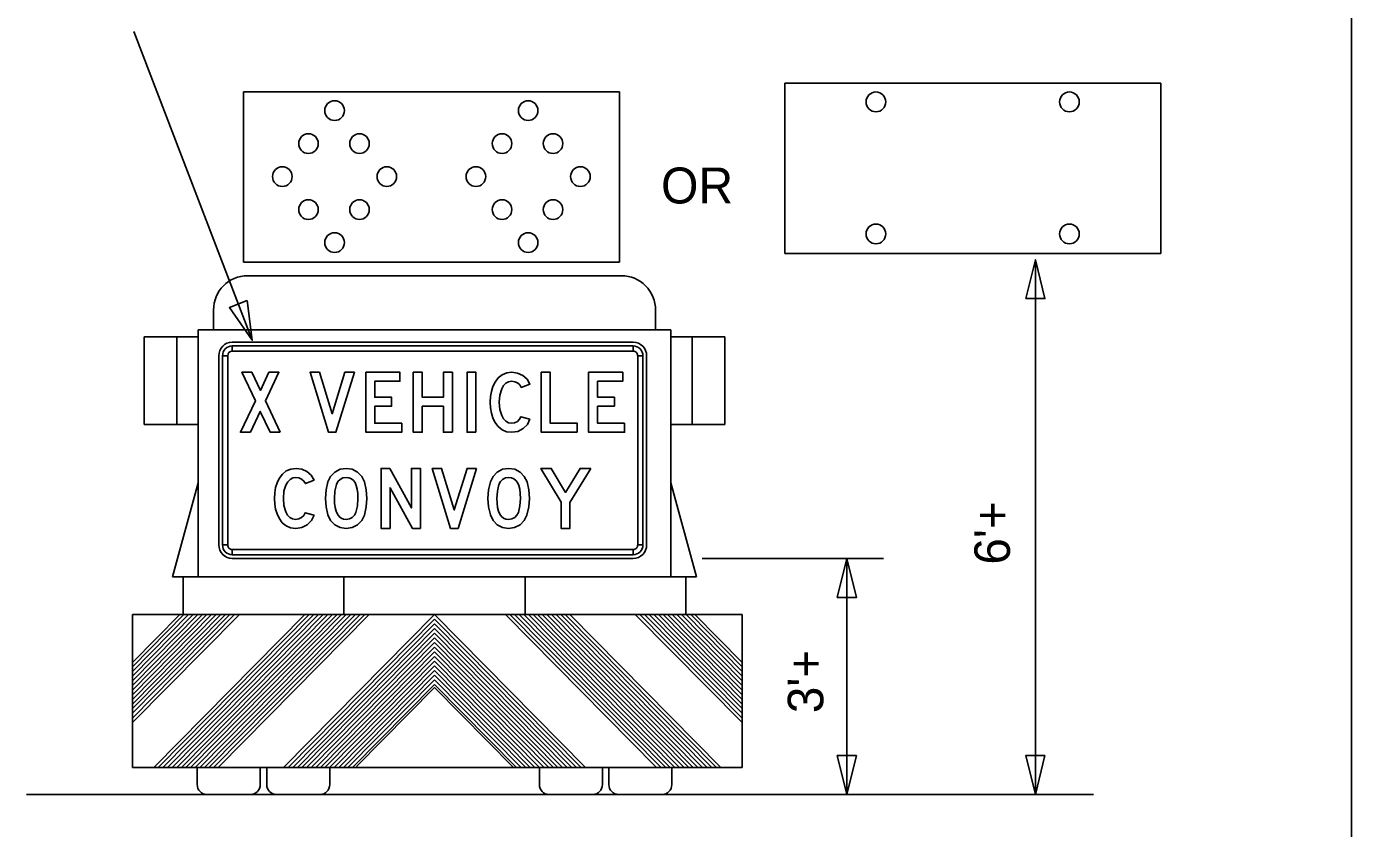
# Model space of a CAD drawing. Extents: x 1416408 to 1429341, y 372694 to 383211.
# Drawn here: x 1427728.6 to 1428099.1, y 373595.9 to 373820.1 of the extents above; entities that cross this region are included whole.
import ezdxf

# ---------------------------------------------------------------- set-up
doc = ezdxf.new("R2010")
doc.units = 0
doc.layers.add('Working Level 1', color=7, linetype='Continuous')

msp = doc.modelspace()

# ---------------------------------------------------------------- linework, layer by layer
at = {"layer": 'Working Level 1'}
for p, q in [((1428099.08, 374447.3), (1428099.08, 372727.17)), ((1427791.75, 373732.38), (1427758.6, 373818.69)), ((1427940.68, 373756.63), (1427940.68, 373804.25)), ((1427940.68, 373804.25), (1428045.73, 373804.25)), ((1428045.73, 373756.63), (1428045.73, 373804.25)), ((1427789.34, 373801.82), (1427894.39, 373801.82)), ((1427789.34, 373754.2), (1427789.34, 373801.82)), ((1427894.39, 373754.2), (1427894.39, 373801.82)), ((1427940.68, 373756.63), (1428045.73, 373756.63)), ((1427789.34, 373754.2), (1427894.39, 373754.2)), ((1428010.69, 373605.38), (1428010.69, 373754.93)), ((1428010.69, 373754.93), (1428010.69, 373746.16)), ((1427790.42, 373750.44), (1427894.99, 373750.44)), ((1427780.92, 373735.32), (1427780.92, 373740.84)), ((1427904.5, 373735.32), (1427904.5, 373740.84)), ((1427776.61, 373666.22), (1427776.61, 373735.32)), ((1427776.61, 373735.32), (1427908.81, 373735.32)), ((1427908.81, 373666.22), (1427908.81, 373735.32)), ((1427761.52, 373708.81), (1427761.52, 373733.37)), ((1427761.52, 373733.37), (1427776.61, 373733.37)), ((1427770.66, 373708.81), (1427770.66, 373733.37)), ((1427898.26, 373731.85), (1427786.12, 373731.85)), ((1427786.12, 373729.33), (1427786.12, 373730.8)), ((1427898.26, 373730.8), (1427898.26, 373729.33)), ((1427923.9, 373733.37), (1427908.81, 373733.37)), ((1427914.76, 373708.81), (1427914.76, 373733.37)), ((1427923.9, 373708.81), (1427923.9, 373733.37)), ((1427782.38, 373728.07), (1427782.38, 373675.16)), ((1427783.42, 373728.07), (1427784.87, 373728.07)), ((1427899.51, 373728.07), (1427900.96, 373728.07)), ((1427902, 373675.16), (1427902, 373728.07)), ((1427761.52, 373708.81), (1427776.61, 373708.81)), ((1427923.9, 373708.81), (1427908.81, 373708.81)), ((1427776.61, 373692.54), (1427769.46, 373666.22)), ((1427908.81, 373692.54), (1427915.96, 373666.22)), ((1427784.87, 373675.16), (1427783.42, 373675.16)), ((1427900.96, 373675.16), (1427899.51, 373675.16)), ((1427786.12, 373672.43), (1427786.12, 373673.9)), ((1427786.12, 373671.38), (1427898.26, 373671.38)), ((1427898.26, 373673.9), (1427898.26, 373672.43)), ((1427917.53, 373671.38), (1427968.23, 373671.38)), ((1427958.01, 373605.38), (1427958.01, 373671.38)), ((1427958.01, 373671.38), (1427958.01, 373662.47)), ((1427769.46, 373666.22), (1427915.96, 373666.22)), ((1427772.43, 373655.67), (1427772.43, 373666.22)), ((1427817.34, 373655.67), (1427817.34, 373666.03)), ((1427868.08, 373655.67), (1427868.08, 373666.03)), ((1427912.99, 373655.67), (1427912.99, 373666.22)), ((1427758.23, 373655.67), (1427928.73, 373655.67)), ((1427758.23, 373655.67), (1427928.73, 373655.67)), ((1427758.23, 373655.67), (1427928.73, 373655.67)), ((1427758.23, 373655.67), (1427928.73, 373655.67)), ((1427758.23, 373612.98), (1427758.23, 373655.67)), ((1427758.23, 373642.31), (1427771.45, 373655.67)), ((1427758.23, 373626.77), (1427786.82, 373655.67)), ((1427758.23, 373628.08), (1427785.52, 373655.67)), ((1427758.23, 373629.39), (1427784.23, 373655.67)), ((1427758.23, 373630.68), (1427782.96, 373655.67)), ((1427758.23, 373631.98), (1427781.66, 373655.67)), ((1427758.23, 373633.29), (1427780.37, 373655.67)), ((1427758.23, 373634.58), (1427779.09, 373655.67)), ((1427758.23, 373635.89), (1427777.8, 373655.67)), ((1427758.23, 373637.2), (1427776.51, 373655.67)), ((1427758.23, 373638.5), (1427775.21, 373655.67)), ((1427758.23, 373639.79), (1427773.94, 373655.67)), ((1427758.23, 373641.1), (1427772.64, 373655.67)), ((1427758.23, 373625.47), (1427788.07, 373655.63)), ((1427764.18, 373612.98), (1427806.41, 373655.67)), ((1427765.47, 373612.98), (1427807.7, 373655.67)), ((1427766.76, 373612.98), (1427808.99, 373655.67)), ((1427768.05, 373612.98), (1427810.28, 373655.67)), ((1427769.33, 373612.98), (1427811.56, 373655.67)), ((1427770.62, 373612.98), (1427812.85, 373655.67)), ((1427771.92, 373612.98), (1427814.14, 373655.67)), ((1427773.21, 373612.98), (1427815.44, 373655.67)), ((1427774.48, 373612.98), (1427816.71, 373655.67)), ((1427775.78, 373612.98), (1427818.01, 373655.67)), ((1427777.07, 373612.98), (1427819.3, 373655.67)), ((1427778.35, 373612.98), (1427820.57, 373655.67)), ((1427779.64, 373612.98), (1427821.87, 373655.67)), ((1427780.93, 373612.98), (1427823.14, 373655.65)), ((1427782.22, 373612.98), (1427824.45, 373655.67)), ((1427800.48, 373612.98), (1427842.71, 373655.67)), ((1427801.77, 373612.98), (1427842.71, 373654.37)), ((1427803.06, 373612.98), (1427842.71, 373653.06)), ((1427884.94, 373612.98), (1427842.71, 373655.67)), ((1427883.59, 373613.05), (1427842.71, 373654.37)), ((1427882.37, 373612.98), (1427842.71, 373653.06)), ((1427904.75, 373612.98), (1427862.52, 373655.67)), ((1427906.03, 373612.98), (1427863.82, 373655.65)), ((1427907.33, 373612.98), (1427865.1, 373655.67)), ((1427908.62, 373612.98), (1427866.39, 373655.67)), ((1427909.9, 373612.98), (1427867.67, 373655.67)), ((1427911.19, 373612.98), (1427868.96, 373655.67)), ((1427912.48, 373612.98), (1427870.25, 373655.67)), ((1427913.76, 373612.98), (1427871.53, 373655.67)), ((1427915.05, 373612.98), (1427872.82, 373655.67)), ((1427916.34, 373612.98), (1427874.12, 373655.67)), ((1427917.64, 373612.98), (1427875.41, 373655.67)), ((1427918.91, 373612.98), (1427876.69, 373655.67)), ((1427920.21, 373612.98), (1427877.98, 373655.67)), ((1427921.5, 373612.98), (1427879.27, 373655.67)), ((1427922.78, 373612.98), (1427880.56, 373655.67)), ((1427928.73, 373625.47), (1427898.9, 373655.63)), ((1427928.73, 373626.77), (1427900.15, 373655.67)), ((1427928.73, 373628.08), (1427901.44, 373655.67)), ((1427928.73, 373629.39), (1427902.74, 373655.67)), ((1427928.73, 373630.68), (1427904.01, 373655.67)), ((1427928.73, 373631.98), (1427905.3, 373655.67)), ((1427928.73, 373633.29), (1427906.6, 373655.67)), ((1427928.73, 373634.58), (1427907.87, 373655.67)), ((1427928.73, 373635.89), (1427909.17, 373655.67)), ((1427928.73, 373637.2), (1427910.46, 373655.67)), ((1427928.73, 373638.5), (1427911.75, 373655.67)), ((1427928.73, 373639.79), (1427913.03, 373655.67)), ((1427928.73, 373641.1), (1427914.32, 373655.67)), ((1427928.73, 373642.31), (1427915.52, 373655.67)), ((1427928.73, 373612.98), (1427928.73, 373655.67)), ((1427804.35, 373612.98), (1427842.71, 373651.76)), ((1427805.63, 373612.98), (1427842.71, 373650.47)), ((1427806.92, 373612.98), (1427842.71, 373649.16)), ((1427881.08, 373612.98), (1427842.71, 373651.76)), ((1427879.8, 373612.98), (1427842.71, 373650.47)), ((1427878.51, 373612.98), (1427842.71, 373649.16)), ((1427808.21, 373612.98), (1427842.71, 373647.85)), ((1427809.49, 373612.98), (1427842.71, 373646.56)), ((1427810.78, 373612.98), (1427842.71, 373645.26)), ((1427877.21, 373612.98), (1427842.71, 373647.85)), ((1427875.94, 373612.98), (1427842.71, 373646.56)), ((1427874.64, 373612.98), (1427842.71, 373645.26)), ((1427812.08, 373612.98), (1427842.71, 373643.95)), ((1427813.37, 373612.98), (1427842.71, 373642.64)), ((1427814.65, 373612.98), (1427842.71, 373641.35)), ((1427873.35, 373612.98), (1427842.71, 373643.95)), ((1427872.06, 373612.98), (1427842.71, 373642.64)), ((1427870.78, 373612.98), (1427842.71, 373641.35)), ((1427815.94, 373612.98), (1427842.71, 373640.04)), ((1427817.23, 373612.98), (1427842.71, 373638.73)), ((1427818.51, 373612.98), (1427842.71, 373637.45)), ((1427869.49, 373612.98), (1427842.71, 373640.04)), ((1427868.2, 373612.98), (1427842.71, 373638.73)), ((1427866.92, 373612.98), (1427842.71, 373637.45)), ((1427819.79, 373612.98), (1427842.71, 373636.15)), ((1427820.88, 373613.23), (1427842.71, 373635.3)), ((1427865.63, 373612.98), (1427842.71, 373636.15)), ((1427864.79, 373612.98), (1427842.71, 373635.3)), ((1427758.23, 373612.98), (1427928.73, 373612.98)), ((1427758.23, 373612.98), (1427928.73, 373612.98)), ((1427758.23, 373612.98), (1427928.73, 373612.98)), ((1427758.23, 373612.98), (1427928.73, 373612.98)), ((1427776.35, 373608.14), (1427776.35, 373612.98)), ((1427793.97, 373608.14), (1427793.97, 373612.98)), ((1427795.79, 373608.14), (1427795.79, 373612.98)), ((1427813.41, 373608.14), (1427813.41, 373612.98)), ((1427872.01, 373608.14), (1427872.01, 373612.98)), ((1427889.63, 373608.14), (1427889.63, 373612.98)), ((1427891.45, 373608.14), (1427891.45, 373612.98)), ((1427909.07, 373608.14), (1427909.07, 373612.98)), ((1427728.62, 373605.38), (1428026.92, 373605.38)), ((1427776.35, 373605.38), (1427793.97, 373605.38)), ((1427776.35, 373605.38), (1427793.97, 373605.38)), ((1427776.35, 373605.38), (1427793.97, 373605.38)), ((1427776.35, 373605.38), (1427793.97, 373605.38)), ((1427795.79, 373605.38), (1427813.41, 373605.38)), ((1427795.79, 373605.38), (1427813.41, 373605.38)), ((1427795.79, 373605.38), (1427813.41, 373605.38)), ((1427795.79, 373605.38), (1427813.41, 373605.38)), ((1427889.63, 373605.38), (1427872.01, 373605.38)), ((1427889.63, 373605.38), (1427872.01, 373605.38)), ((1427889.63, 373605.38), (1427872.01, 373605.38)), ((1427889.63, 373605.38), (1427872.01, 373605.38)), ((1427909.07, 373605.38), (1427891.45, 373605.38)), ((1427909.07, 373605.38), (1427891.45, 373605.38)), ((1427909.07, 373605.38), (1427891.45, 373605.38)), ((1427909.07, 373605.38), (1427891.45, 373605.38))]:
    msp.add_line(p, q, dxfattribs=at)
for points in [[(1428008, 373744.04), (1428010.69, 373754.93), (1428013.38, 373744.04)], [(1427790.36, 373743.51), (1427791.75, 373732.38), (1427785.34, 373741.54)], [(1427898.26, 373730.8), (1427786.12, 373730.8), (1427786.12, 373729.33), (1427898.26, 373729.33), (1427898.26, 373730.8)], [(1427783.42, 373728.07), (1427783.42, 373675.16), (1427784.87, 373675.16), (1427784.87, 373728.07), (1427783.42, 373728.07)], [(1427900.96, 373675.16), (1427900.96, 373728.07), (1427899.51, 373728.07), (1427899.51, 373675.16), (1427900.96, 373675.16)], [(1427799.54, 373706.66), (1427795.41, 373715.45), (1427799.2, 373723.45), (1427796.42, 373723.45), (1427794.01, 373718.38), (1427791.62, 373723.45), (1427788.84, 373723.45), (1427792.62, 373715.43), (1427788.45, 373706.66), (1427791.23, 373706.66), (1427794, 373712.49), (1427796.77, 373706.66)], [(1427820.3, 373723.45), (1427817.67, 373723.45), (1427814.1, 373711.85), (1427810.54, 373723.45), (1427807.92, 373723.45), (1427813.07, 373706.66), (1427815.13, 373706.66)], [(1427833.54, 373709.19), (1427826.01, 373709.19), (1427826.01, 373713.95), (1427830.71, 373713.95), (1427830.71, 373716.48), (1427826.01, 373716.48), (1427826.01, 373720.92), (1427833.04, 373720.92), (1427833.04, 373723.45), (1427823.5, 373723.45), (1427823.5, 373706.66), (1427833.54, 373706.66)], [(1427847.71, 373706.66), (1427847.71, 373723.45), (1427845.2, 373723.45), (1427845.2, 373716.48), (1427839.25, 373716.48), (1427839.25, 373723.45), (1427836.74, 373723.45), (1427836.74, 373706.66), (1427839.25, 373706.66), (1427839.25, 373713.95), (1427845.2, 373713.95), (1427845.2, 373706.66)], [(1427854.3, 373706.66), (1427854.3, 373723.45), (1427851.8, 373723.45), (1427851.8, 373706.66)], [(1427869.37, 373710.38), (1427866.86, 373711.03), (1427866.49, 373710.29), (1427865.88, 373709.71), (1427865.1, 373709.32), (1427864.24, 373709.19), (1427863.37, 373709.32), (1427862.62, 373709.73), (1427861.98, 373710.4), (1427861.48, 373711.33), (1427860.96, 373713.05), (1427860.79, 373715.05), (1427860.97, 373717.07), (1427861.49, 373718.79), (1427862.02, 373719.72), (1427862.67, 373720.38), (1427863.43, 373720.78), (1427864.32, 373720.92), (1427865.15, 373720.8), (1427865.91, 373720.45), (1427866.54, 373719.9), (1427866.97, 373719.2), (1427869.37, 373720.16), (1427868.56, 373721.5), (1427867.38, 373722.55), (1427865.94, 373723.22), (1427864.36, 373723.45), (1427862.9, 373723.28), (1427861.62, 373722.75), (1427860.53, 373721.87), (1427859.62, 373720.65), (1427859.04, 373719.44), (1427858.62, 373718.1), (1427858.37, 373716.64), (1427858.29, 373715.06), (1427858.36, 373713.49), (1427858.61, 373712.03), (1427859.03, 373710.7), (1427859.61, 373709.49), (1427860.5, 373708.25), (1427861.57, 373707.36), (1427862.83, 373706.83), (1427864.28, 373706.66), (1427865.97, 373706.91), (1427867.48, 373707.69), (1427868.67, 373708.88)], [(1427882.61, 373706.66), (1427882.61, 373709.19), (1427875.07, 373709.19), (1427875.07, 373723.45), (1427872.56, 373723.45), (1427872.56, 373706.66)], [(1427895.85, 373709.19), (1427888.31, 373709.19), (1427888.31, 373713.95), (1427893.01, 373713.95), (1427893.01, 373716.48), (1427888.31, 373716.48), (1427888.31, 373720.92), (1427895.34, 373720.92), (1427895.34, 373723.45), (1427885.8, 373723.45), (1427885.8, 373706.66), (1427895.85, 373706.66)], [(1427809.02, 373683.51), (1427806.51, 373684.15), (1427806.13, 373683.41), (1427805.53, 373682.83), (1427804.75, 373682.45), (1427803.88, 373682.32), (1427803.01, 373682.45), (1427802.26, 373682.85), (1427801.63, 373683.52), (1427801.12, 373684.45), (1427800.6, 373686.18), (1427800.44, 373688.18), (1427800.61, 373690.19), (1427801.14, 373691.92), (1427801.66, 373692.84), (1427802.31, 373693.51), (1427803.07, 373693.91), (1427803.96, 373694.04), (1427804.79, 373693.92), (1427805.55, 373693.58), (1427806.18, 373693.03), (1427806.61, 373692.32), (1427809.02, 373693.28), (1427808.2, 373694.63), (1427807.02, 373695.68), (1427805.58, 373696.35), (1427804, 373696.58), (1427802.54, 373696.4), (1427801.26, 373695.88), (1427800.17, 373695), (1427799.27, 373693.78), (1427798.68, 373692.56), (1427798.26, 373691.23), (1427798.01, 373689.77), (1427797.93, 373688.19), (1427798.01, 373686.61), (1427798.26, 373685.15), (1427798.67, 373683.82), (1427799.25, 373682.61), (1427800.14, 373681.37), (1427801.22, 373680.49), (1427802.48, 373679.95), (1427803.92, 373679.78), (1427805.61, 373680.04), (1427807.13, 373680.81), (1427808.31, 373682.01)], [(1427823.8, 373688.19), (1427823.63, 373690.59), (1427823.13, 373692.83), (1427822.38, 373694.34), (1427821.19, 373695.54), (1427819.69, 373696.31), (1427818, 373696.58), (1427816.31, 373696.31), (1427814.81, 373695.54), (1427813.63, 373694.34), (1427812.88, 373692.81), (1427812.37, 373690.57), (1427812.21, 373688.19), (1427812.37, 373685.81), (1427812.88, 373683.56), (1427813.63, 373682.03), (1427814.81, 373680.83), (1427816.31, 373680.04), (1427818, 373679.78), (1427819.68, 373680.04), (1427821.18, 373680.81), (1427822.36, 373682.01), (1427823.12, 373683.53), (1427823.63, 373685.78)], [(1427821.3, 373688.18), (1427821.15, 373686.14), (1427820.71, 373684.24), (1427820.31, 373683.45), (1427819.69, 373682.84), (1427818.9, 373682.45), (1427818.02, 373682.32), (1427817.24, 373682.4), (1427816.57, 373682.68), (1427816, 373683.14), (1427815.54, 373683.78), (1427815.18, 373684.6), (1427814.92, 373685.61), (1427814.76, 373686.8), (1427814.71, 373688.18), (1427814.86, 373690.21), (1427815.3, 373692.1), (1427815.7, 373692.89), (1427816.32, 373693.51), (1427817.11, 373693.91), (1427818.02, 373694.04), (1427818.78, 373693.95), (1427819.45, 373693.68), (1427820.01, 373693.22), (1427820.47, 373692.58), (1427820.83, 373691.75), (1427821.09, 373690.75), (1427821.24, 373689.55)], [(1427838.75, 373679.78), (1427838.75, 373696.58), (1427836.25, 373696.58), (1427836.25, 373685.54), (1427830.19, 373696.58), (1427827.78, 373696.58), (1427827.78, 373679.78), (1427830.29, 373679.78), (1427830.29, 373691.18), (1427836.54, 373679.78)], [(1427854.43, 373696.58), (1427851.81, 373696.58), (1427848.24, 373684.97), (1427844.68, 373696.58), (1427842.06, 373696.58), (1427847.21, 373679.78), (1427849.27, 373679.78)], [(1427869.23, 373688.19), (1427869.06, 373690.59), (1427868.56, 373692.83), (1427867.81, 373694.34), (1427866.62, 373695.54), (1427865.12, 373696.31), (1427863.43, 373696.58), (1427861.74, 373696.31), (1427860.24, 373695.54), (1427859.06, 373694.34), (1427858.31, 373692.81), (1427857.8, 373690.57), (1427857.64, 373688.19), (1427857.8, 373685.81), (1427858.31, 373683.56), (1427859.06, 373682.03), (1427860.24, 373680.83), (1427861.74, 373680.04), (1427863.43, 373679.78), (1427865.11, 373680.04), (1427866.61, 373680.81), (1427867.79, 373682.01), (1427868.54, 373683.53), (1427869.06, 373685.78)], [(1427866.73, 373688.18), (1427866.58, 373686.14), (1427866.14, 373684.24), (1427865.74, 373683.45), (1427865.12, 373682.84), (1427864.33, 373682.45), (1427863.45, 373682.32), (1427862.67, 373682.4), (1427862, 373682.68), (1427861.43, 373683.14), (1427860.97, 373683.78), (1427860.6, 373684.6), (1427860.35, 373685.61), (1427860.19, 373686.8), (1427860.14, 373688.18), (1427860.29, 373690.21), (1427860.73, 373692.1), (1427861.13, 373692.89), (1427861.75, 373693.51), (1427862.54, 373693.91), (1427863.45, 373694.04), (1427864.21, 373693.95), (1427864.88, 373693.68), (1427865.44, 373693.22), (1427865.9, 373692.58), (1427866.26, 373691.75), (1427866.52, 373690.75), (1427866.67, 373689.55)], [(1427886.36, 373696.58), (1427883.41, 373696.58), (1427879.34, 373689.87), (1427875.35, 373696.58), (1427872.43, 373696.58), (1427878.08, 373687.14), (1427878.08, 373679.78), (1427880.58, 373679.78), (1427880.58, 373687.07)], [(1427786.12, 373672.43), (1427898.26, 373672.43), (1427898.26, 373673.9), (1427786.12, 373673.9), (1427786.12, 373672.43)], [(1427955.32, 373660.5), (1427958.01, 373671.38), (1427960.7, 373660.5)], [(1427960.7, 373616.26), (1427958.01, 373605.38), (1427955.32, 373616.26)], [(1428013.38, 373616.26), (1428010.69, 373605.38), (1428008, 373616.26)]]:
    msp.add_lwpolyline(points, close=True, dxfattribs=at)
for centre, major_axis in [((1427966.11, 373799.05), (0, 2.77)), ((1428020.22, 373799.05), (0, 2.77)), ((1427814.76, 373796.62), (0, 2.77)), ((1427868.88, 373796.62), (0, 2.77)), ((1427807.46, 373787.39), (0, 2.77)), ((1427821.73, 373787.39), (0, -2.77)), ((1427861.58, 373787.39), (0, 2.77)), ((1427875.84, 373787.39), (0, -2.77)), ((1427800.16, 373778.16), (0, -2.77)), ((1427829.37, 373778.16), (0, 2.77)), ((1427854.28, 373778.16), (0, -2.77)), ((1427883.49, 373778.16), (0, 2.77)), ((1427807.46, 373768.93), (0, 2.77)), ((1427821.73, 373768.93), (0, -2.77)), ((1427861.58, 373768.93), (0, 2.77)), ((1427875.84, 373768.93), (0, -2.77)), ((1427966.11, 373762.13), (0, 2.77)), ((1428020.22, 373762.13), (0, 2.77)), ((1427814.76, 373759.7), (0, 2.77)), ((1427868.88, 373759.7), (0, 2.77))]:
    msp.add_ellipse(centre, major_axis=major_axis, ratio=0.989089, dxfattribs=at)
for centre, major_axis, start_param, end_param in [((1427790.42, 373740.84), (0, 9.61), 6.283185, 7.853981), ((1427895, 373740.84), (0, 9.61), 4.712389, 6.283186), ((1427786.12, 373728.07), (0, 3.78), 0.000004, 1.570794), ((1427786.12, 373728.07), (0, 2.73), 0.000004, 1.570794), ((1427898.26, 373728.07), (0, 3.78), 4.712389, 6.283189), ((1427898.26, 373728.07), (0, 2.73), 4.712389, 6.283189), ((1427786.12, 373728.07), (0, 1.26), 0.000004, 1.570794), ((1427898.26, 373728.07), (0, 1.26), 4.712389, 6.283189), ((1427786.12, 373675.16), (0, 3.78), 1.570794, 3.141594), ((1427786.12, 373675.16), (0, 2.73), 1.570794, 3.141594), ((1427786.12, 373675.16), (0, 1.26), 1.570794, 3.141594), ((1427898.26, 373675.16), (0, 3.78), 3.141594, 4.712394), ((1427898.26, 373675.16), (0, 2.73), 3.141594, 4.712394), ((1427898.26, 373675.16), (0, 1.26), 3.141594, 4.712394), ((1427779.08, 373608.14), (0, -2.76), 4.712389, 6.283185), ((1427791.24, 373608.14), (0, 2.76), 3.141593, 4.712389), ((1427798.52, 373608.14), (0, -2.76), 4.712389, 6.283185), ((1427810.67, 373608.14), (0, 2.76), 3.141593, 4.712389), ((1427874.74, 373608.14), (0, -2.76), 4.712389, 6.283185), ((1427886.9, 373608.14), (0, 2.76), 3.141593, 4.712389), ((1427894.18, 373608.14), (0, -2.76), 4.712389, 6.283185), ((1427906.33, 373608.14), (0, 2.76), 3.141593, 4.712389)]:
    msp.add_ellipse(centre, major_axis=major_axis, ratio=0.989089, start_param=start_param, end_param=end_param, dxfattribs=at)

# ---------------------------------------------------------------- texts
msp.add_text('OR', height=10.046, dxfattribs=at).set_placement((1427906.04, 373770.65))
for s, p in [("6'+", (1428003.58, 373669.67)), ("3'+", (1427951.41, 373628.14))]:
    msp.add_text(s, height=9.937, rotation=90, dxfattribs=at).set_placement(p)

doc.saveas('drawing.dxf')
